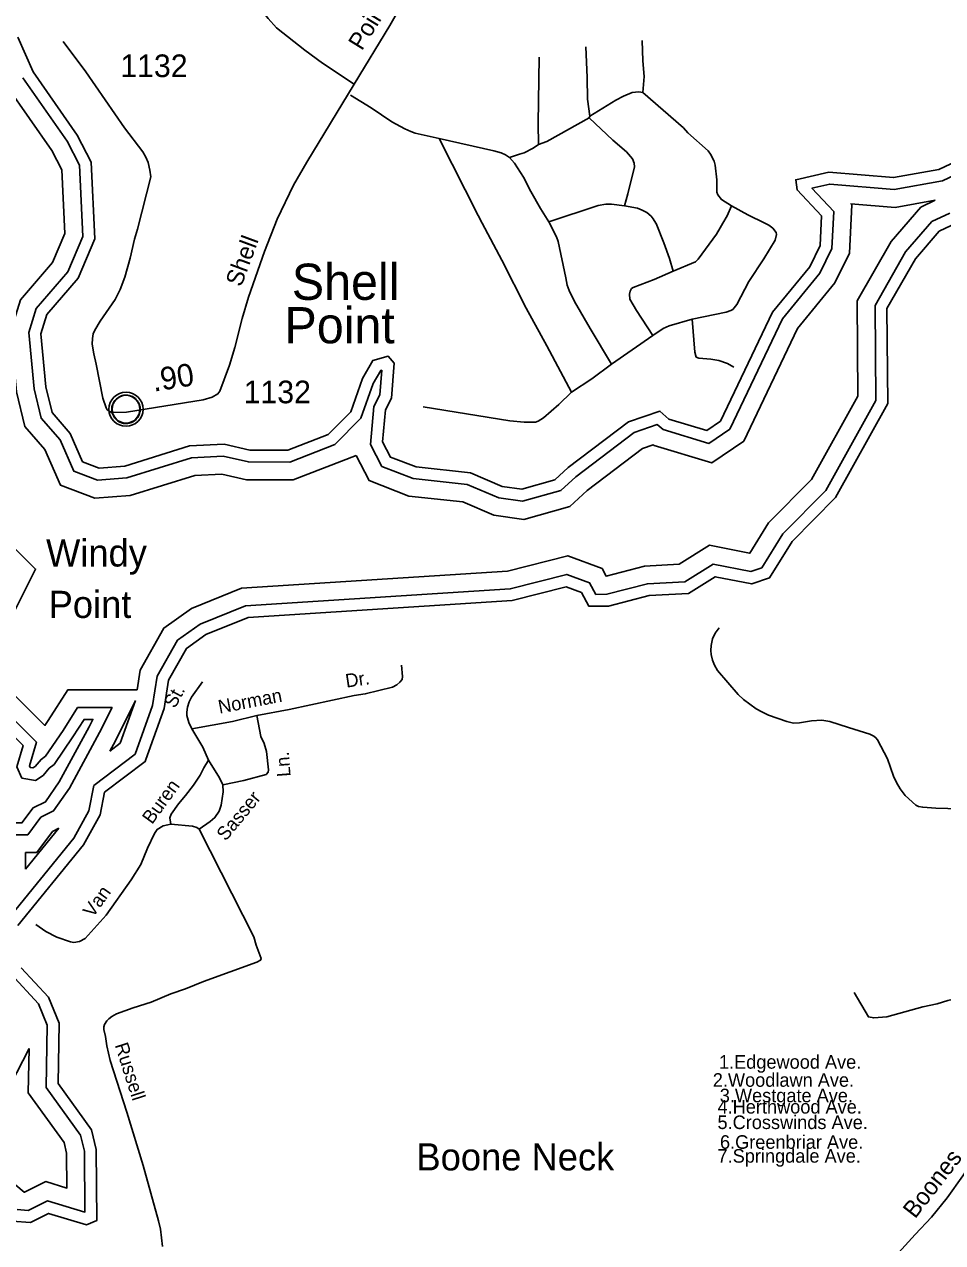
# Model space of a CAD drawing. Extents: x 2104537 to 2336408, y 34176 to 229611.
# Drawn here: x 2193537 to 2198609, y 61547 to 68278 of the extents above; entities that cross this region are included whole.
import ezdxf

# ---------------------------------------------------------------- set-up
doc = ezdxf.new("R2010")
doc.units = 0
for name, color, linetype in [('Exist Civil Demographics Community CELL', 7, 'Continuous'), ('Exist Civil Demographics Community Label', 7, 'Continuous'), ('Exist Hydrographic Buffer Line', 7, 'Continuous'), ('Exist Hydrographic Island Shore', 7, 'Continuous'), ('Exist Hydrographic Point Label', 7, 'Continuous'), ('Exist Hydrographic River Shore', 7, 'Continuous'), ('Exist Road Non-System Type 51', 7, 'Continuous'), ('Exist Road Non-System Type 51 Label', 7, 'Continuous'), ('Exist Road Secondary Mileage Hundredths English Label', 7, 'Continuous'), ('Exist Road Secondary Type 51 Attributed', 7, 'Continuous'), ('Exist Road Secondary Type 51 Label', 7, 'Continuous'), ('Exist Road Secondary Type 51 Number Label', 7, 'Continuous')]:
    doc.layers.add(name, color=color, linetype=linetype)

msp = doc.modelspace()

# ---------------------------------------------------------------- linework, layer by layer
at = {"layer": 'Exist Civil Demographics Community CELL'}
msp.add_lwpolyline([(2194021.1, 66163.6), (2194022.1, 66169.2), (2194023.9, 66175.8), (2194026.8, 66183), (2194029.7, 66188.7), (2194033.1, 66194.5), (2194036.8, 66199.6), (2194040.8, 66204), (2194045.4, 66208.6), (2194050.9, 66213.2), (2194056.3, 66216.8), (2194061.2, 66219.7), (2194066.3, 66222.1), (2194071.7, 66224.4), (2194077.4, 66226.3), (2194081.7, 66227.4), (2194086.5, 66228.1), (2194090.7, 66228.9), (2194097, 66229.1), (2194101.5, 66229), (2194107.1, 66228.8), (2194112, 66228), (2194116.9, 66227), (2194122, 66225.6), (2194127.1, 66223.7), (2194133.8, 66220.8), (2194140, 66217.3), (2194145.1, 66213.7), (2194150.3, 66209.7), (2194153.6, 66206.6), (2194157.7, 66202.2), (2194161.6, 66197.5), (2194164.6, 66192.9), (2194167.8, 66187.9), (2194170.2, 66182.7), (2194172.3, 66177.7), (2194173.8, 66172.7), (2194175.1, 66168.1), (2194176.2, 66162.1), (2194176.8, 66157.4), (2194177.1, 66151.4), (2194176.9, 66145.6), (2194176.3, 66139.9), (2194175.4, 66134.4), (2194173.7, 66128.3), (2194171.9, 66122.4), (2194169.6, 66117.4), (2194166.4, 66111.4), (2194163.1, 66106), (2194159.7, 66101.3), (2194155.4, 66096.6), (2194150.2, 66091.6), (2194145.1, 66087.5), (2194140.1, 66084.1), (2194135.8, 66081.6), (2194129, 66078.3), (2194121.8, 66075.6), (2194115.9, 66074.2), (2194109.3, 66072.9), (2194104.9, 66072.4), (2194100.4, 66072.1), (2194094.8, 66072.1), (2194090.5, 66072.5), (2194084.9, 66073.3), (2194079, 66074.6), (2194074.4, 66075.9), (2194069.2, 66077.8), (2194064.6, 66079.7), (2194060.7, 66082), (2194053.9, 66086.1), (2194048.3, 66090.3), (2194043.4, 66094.8), (2194038.9, 66099.7), (2194035.8, 66103.6), (2194032.8, 66107.8), (2194028.7, 66114.9), (2194027, 66118.5), (2194025.2, 66122.5), (2194022.7, 66130.7), (2194021.1, 66137.7), (2194020.4, 66142.9), (2194020.1, 66149.2), (2194020, 66153.9), (2194020.6, 66160.4)], close=True, dxfattribs=at)
for centre, radius in [((2194098.7, 66151.2), 94.3), ((2194098.5, 66151.5), 76.7)]:
    msp.add_circle(centre, radius, dxfattribs=at)
at = {"layer": 'Exist Hydrographic Buffer Line'}
for points in [[(2195369.5, 65896), (2195022.3, 65760.4), (2194764, 65761.3), (2194627.2, 65792.6), (2194478.6, 65785.3), (2194122.5, 65674.7), (2193926.7, 65660.3), (2193736.3, 65731.9), (2193650.3, 65928.4), (2193540.7, 66056.2), (2193493.6, 66247.8), (2193462.4, 66584.7), (2193515, 66756.4), (2193693.3, 66962.7), (2193760.1, 67122.6), (2193743.6, 67473.9), (2193688.7, 67581.4), (2193442.1, 67934.4), (2193346.9, 68149.6), (2193298.6, 68305.6)], [(2198907, 67554.4), (2198608.9, 67412.9), (2198341.8, 67365.4), (2197985.5, 67395.1), (2197887.1, 67372.3), (2198007.7, 67244), (2197997.7, 67038.9), (2197931.4, 66902.8), (2197724.7, 66651.1), (2197433.4, 66040.9), (2197317.8, 65962.2), (2197065.3, 66038.4), (2197033.1, 66066.5), (2196904.9, 66023.1), (2196583.8, 65778.6), (2196500.5, 65702.7), (2196289.5, 65642.4), (2196157.8, 65660.8), (2195983.9, 65735.9), (2195685.1, 65767.8), (2195511.8, 65835.2), (2195448.8, 65957.1), (2195467.6, 66165.6), (2195500.4, 66230.1), (2195511, 66366.6), (2195506.5, 66365.3), (2195464.5, 66292.5), (2195396.6, 66101.9), (2195252.7, 65956.1), (2195004, 65858.9), (2194775.2, 65859.7), (2194635.9, 65891.5), (2194461.3, 65882.9), (2194104, 65772), (2193941.1, 65760), (2193809.8, 65809.4), (2193734.5, 65981.3), (2193630.7, 66102.5), (2193590.9, 66264.2), (2193562.2, 66574.4), (2193603.1, 66707.7), (2193778.1, 66910.3), (2193859.4, 67105.1), (2193840.9, 67499.8), (2193773.3, 67632.2), (2193528.2, 67982.9)], [(2194159.6, 64601.1), (2194176.1, 64708.9), (2194307.8, 64941.9), (2194460.2, 65051.1), (2194735.9, 65162.3), (2196205.1, 65256.3), (2196538.9, 65341.4), (2196727.9, 65271.2), (2196750.8, 65229.7), (2196963.4, 65284.5), (2197153.9, 65295.3), (2197322.2, 65399.6), (2197543.2, 65355.7), (2197544.8, 65356.2), (2197648.1, 65523.6), (2197885.5, 65762.3), (2198141.4, 66224), (2198137.5, 66750), (2198324.2, 67078.3), (2198489.4, 67268.1), (2198568.2, 67305.7)], [(2198568.2, 67305.7), (2198346.4, 67266.3), (2198102.7, 67286.6), (2198108, 67280.9), (2198095, 67013.9), (2198014.8, 66849.3), (2197808.3, 66597.9), (2197510.7, 65974.5), (2197334.3, 65854.4), (2197016.6, 65950.3), (2197011, 65955.2), (2196951.7, 65935.1), (2196646.8, 65702.9), (2196549.7, 65614.4), (2196296.5, 65542.1), (2196131, 65565.1), (2195958.6, 65639.6), (2195661.7, 65671.3), (2195441.5, 65756.9), (2195369.5, 65896)], [(2194148.6, 64244.7), (2194245.8, 64513.6), (2194270.7, 64676.2), (2194382.7, 64874.6), (2194508, 64964.3), (2194758, 65065.1), (2196220.6, 65158.7), (2196533.4, 65238.5), (2196659.4, 65191.7), (2196694.2, 65128.5), (2196755.1, 65129.1), (2196978.6, 65186.8), (2197184.5, 65198.4), (2197341.1, 65295.5), (2197550.2, 65254), (2197610.1, 65274.7), (2197725.9, 65462.3), (2197964.9, 65702.6), (2198240, 66198.9), (2198236.1, 66724.3), (2198404.9, 67021.1), (2198550.2, 67188), (2198648.8, 67235)], [(2192699.6, 65357.9), (2192995.2, 65136.1), (2193188.5, 65007.1), (2193476, 65021.5), (2193599.1, 65268), (2193420.8, 65446.5), (2193358.9, 65454.2), (2193320.5, 65487.2), (2193152.1, 65534), (2193025.9, 65553.4), (2192788, 65510.1)], [(2194159.6, 64601.1), (2193777.8, 64601.1), (2193668.6, 64431.2), (2193650.4, 64404.4), (2193447.7, 64607.3)], [(2193468.3, 64447.3), (2193329.6, 64209.4), (2193270.3, 64114.3), (2193335.3, 64038.3), (2193349.4, 64000.8), (2193363.2, 63904.4), (2193402.3, 63800.1), (2193556.2, 63800.1), (2193628.5, 63896.6), (2193698.6, 63931.6), (2193785.8, 64058.5), (2193953.1, 64365.4), (2194021.7, 64502.7), (2193831.5, 64502.7), (2193750.7, 64376.9), (2193654.2, 64235.2), (2193629.2, 64216.5), (2193596, 64176.6), (2193584.7, 64169.1), (2193569.3, 64171.9), (2193565.6, 64180.1), (2193604.2, 64311.4), (2193468.3, 64447.3)], [(2194009.1, 64262.6), (2194040.3, 64319.8), (2194151.6, 64542.5)], [(2194065.9, 64305.6), (2194151.6, 64542.5)], [(2194009.1, 64262.6), (2194065.9, 64305.6)], [(2193441.6, 63329.1), (2193810.1, 63781.6), (2193893.3, 63933), (2193920.1, 64071.7), (2194148.6, 64244.7)], [(2193543, 63609.4), (2193727.5, 63836)], [(2193543, 63701.7), (2193605.5, 63701.7), (2193693.4, 63818.9), (2193727.5, 63836)], [(2193543, 63609.4), (2193543, 63701.7)], [(2193496.8, 61729.4), (2193557.7, 61724.2), (2193664.6, 61778.2), (2193871.8, 61715.7), (2193869.1, 62052.4), (2193847.8, 62141.2), (2193657.7, 62404.6), (2193663.8, 62747.4), (2193614.6, 62866.2), (2193461.7, 63031.8)], [(2193127.9, 62215.9), (2193349.7, 62043.5), (2193349.7, 61980.8), (2193536.1, 61824.8), (2193538.2, 61824.7), (2193655.4, 61883.9), (2193772.3, 61848.5), (2193770.8, 62040.4), (2193756.6, 62099.4), (2193558.7, 62373.6), (2193563.1, 62619.7)], [(2193214, 62463.2), (2193390.5, 62286.6), (2193563.1, 62619.7)]]:
    msp.add_lwpolyline(points, dxfattribs=at)
at = {"layer": 'Exist Hydrographic Island Shore'}
msp.add_lwpolyline([(2193482.1, 64340.7), (2193385.8, 64175.5), (2193351.4, 64120.4), (2193392.7, 64072.2), (2193413.3, 64017.1), (2193427.1, 63920.8), (2193447.7, 63865.7), (2193523.4, 63865.7), (2193585.3, 63948.3), (2193654.1, 63982.7), (2193729.8, 64092.9), (2193894.9, 64395.8), (2193915.5, 64437.1), (2193867.4, 64437.1), (2193805.5, 64340.7), (2193702.3, 64189.2), (2193674.8, 64168.6), (2193640.4, 64127.3), (2193599.1, 64099.8), (2193523.4, 64113.5), (2193495.9, 64175.5), (2193530.3, 64292.5), (2193482.1, 64340.7)], dxfattribs=at)
at = {"layer": 'Exist Hydrographic River Shore'}
for points in [[(2198887.7, 67617.8), (2198588.7, 67475.9), (2198338.8, 67431.5), (2197980.8, 67461.4), (2197797.9, 67419), (2197805.8, 67363.1), (2197940.8, 67219.4), (2197932.8, 67055.5), (2197875.8, 66938.5), (2197668.9, 66686.6), (2197381.8, 66085.2), (2197306.8, 66034.1), (2197097.8, 66097.2), (2197047.8, 66140.8), (2196873.7, 66081.8), (2196541.7, 65829), (2196467.7, 65761.6), (2196284.8, 65709.3), (2196175.7, 65724.5), (2196000.8, 65800.1), (2195700.8, 65832.1), (2195558.7, 65887.3), (2195515.8, 65970.2), (2195531.8, 66147.1), (2195564.8, 66212), (2195579.8, 66405.3), (2195545.8, 66445.3), (2195462.7, 66420.7), (2195404.7, 66320.1), (2195339.7, 66137.7), (2195215.8, 66012.1), (2194991.7, 65924.5), (2194782.8, 65925.3), (2194641.7, 65957.5), (2194449.8, 65948.1), (2194091.7, 65836.9), (2193950.7, 65826.5), (2193858.8, 65861.1), (2193790.7, 66016.6), (2193690.7, 66133.3), (2193655.8, 66275.1), (2193628.7, 66567.6), (2193661.7, 66675.3), (2193834.6, 66875.3), (2193925.6, 67093.4), (2193905.8, 67517), (2193829.7, 67666.1), (2193585.7, 68015.3), (2193500.8, 68207.2)], [(2194207.8, 64215.5), (2194309.7, 64497.4), (2194333.7, 64654.4), (2194432.7, 64829.7), (2194539.8, 64906.3), (2194772.7, 65000.3), (2196230.8, 65093.6), (2196529.8, 65169.8), (2196613.7, 65138.7), (2196655.7, 65062.4), (2196763.8, 65063.6), (2196988.7, 65121.6), (2197204.8, 65133.8), (2197353.7, 65226.1), (2197554.9, 65186.2), (2197653.7, 65220.3), (2197777.8, 65421.3), (2198017.9, 65662.8), (2198305.8, 66182.2), (2198301.9, 66707.2), (2198458.7, 66983), (2198590.8, 67134.7), (2198656.8, 67166.2)], [(2193501.8, 63299.1), (2193864.7, 63744.8), (2193955.8, 63910.4), (2193979.8, 64034.6), (2194203.7, 64204.2), (2194207.8, 64215.5)], [(2193470.6, 61665.8), (2193570.7, 61657.3), (2193670.8, 61707.8), (2193879.7, 61644.8), (2193937.7, 61669.9), (2193934.7, 62060.4), (2193908.6, 62169.1), (2193723.7, 62425.3), (2193729.6, 62759.9), (2193670.8, 62902.1), (2193519.6, 63065.8)]]:
    msp.add_lwpolyline(points, dxfattribs=at)
at = {"layer": 'Exist Road Non-System Type 51'}
for p, q in [((2196657, 67762.1), (2196661.1, 67769.9)), ((2196434.6, 67187.4), (2196438.7, 67179.1)), ((2197009.1, 66558.8), (2196781, 66399.8))]:
    msp.add_line(p, q, dxfattribs=at)
for points in [[(2196949.3, 68187.9), (2196952.8, 68076), (2196960, 67990.2), (2196953.3, 67901.8)], [(2196637.7, 68153.9), (2196646.2, 67983.8), (2196647.5, 67864), (2196661.1, 67769.9)], [(2196380.3, 68096.5), (2196375.6, 67730.5), (2196376.9, 67614.7)], [(2195828.4, 67647.2), (2195696.7, 67676.3), (2195671.6, 67685.3), (2195639.4, 67701.1), (2195567, 67739.8), (2195452, 67816.2), (2195338.9, 67887)], [(2196953.3, 67901.8), (2196931.1, 67904.2), (2196895.3, 67901.2), (2196846.6, 67881.2), (2196803.5, 67858.1), (2196661.1, 67769.9)], [(2196953.3, 67901.8), (2197177.9, 67706.8), (2197202.3, 67679.1), (2197313.6, 67578.5), (2197328, 67560.9), (2197347.9, 67522.4), (2197353.7, 67500.3), (2197361.7, 67419.2), (2197362.7, 67351.2), (2197367, 67335.4), (2197387.1, 67309.7), (2197443.5, 67274.5)], [(2196376.9, 67614.7), (2196422.9, 67631.2), (2196657, 67762.1)], [(2196851.4, 67274.5), (2196870.7, 67340.7), (2196906.7, 67491.2), (2196906.4, 67511.3), (2196896.1, 67535.1), (2196863.7, 67572.8), (2196788.5, 67637.9), (2196657, 67762.1)], [(2196217.7, 67542.3), (2196195.7, 67556.5), (2196171.6, 67567.8), (2196131.2, 67579.4), (2195828.4, 67647.2)], [(2195828.4, 67647.2), (2196043.9, 67222.1), (2196066.7, 67179)], [(2196376.9, 67614.7), (2196347.3, 67594.2), (2196297.6, 67567.6), (2196271.6, 67561.2), (2196217.7, 67542.3)], [(2196217.7, 67542.3), (2196244, 67510.6), (2196293.4, 67433.2), (2196334.5, 67354), (2196387.5, 67260.4), (2196434.6, 67187.4)], [(2196851.4, 67274.5), (2196779.4, 67283.7), (2196749.5, 67283.3), (2196706.1, 67277.6), (2196434.6, 67187.4)], [(2197025.2, 67179.3), (2197011.1, 67202.8), (2196999.2, 67217.5), (2196976, 67238.3), (2196949.7, 67251.9), (2196923.9, 67261.6), (2196851.4, 67274.5)], [(2197443.5, 67274.5), (2197418.5, 67219.9), (2197395.7, 67179.4)], [(2197443.5, 67274.5), (2197534.1, 67225.5), (2197627.6, 67179.5)], [(2196066.7, 67179), (2196175.3, 66973.9), (2196308.6, 66709.8), (2196423.4, 66500.9), (2196558.9, 66244.7)], [(2196438.7, 67179.1), (2196475.7, 67103.9), (2196486, 67077.8), (2196528.7, 66876.5), (2196535.2, 66836.3), (2196545.7, 66806.6), (2196576.4, 66747), (2196662.4, 66596.4), (2196781, 66399.8)], [(2197120.3, 66914.3), (2197101.3, 66983.9), (2197070.2, 67071.4), (2197026.6, 67176.9), (2197025.2, 67179.3)], [(2197395.7, 67179.4), (2197381.2, 67153.7), (2197359.5, 67119.3), (2197259.7, 66979.9), (2197243.7, 66965.7), (2197120.3, 66914.3)], [(2197627.6, 67179.5), (2197649.2, 67168.9), (2197671.5, 67151), (2197689.7, 67127.7), (2197691.8, 67117.5), (2197684.3, 67085.2), (2197621.6, 66982.4), (2197539.2, 66857.7), (2197473.1, 66730.7), (2197449.9, 66702.9), (2197439.3, 66696.2), (2197413.2, 66687.9), (2197225.8, 66649.5)], [(2197120.3, 66914.3), (2197016.8, 66868.7), (2196900.4, 66823.7), (2196891.1, 66818), (2196883.6, 66803), (2196880, 66787), (2196882.1, 66759.1), (2196919, 66697.4), (2197009.1, 66558.8)], [(2197225.8, 66649.5), (2197098.7, 66611.9), (2197066.6, 66597.4), (2197009.1, 66558.8)], [(2197455.6, 66384.5), (2197421.2, 66403.9), (2197372.6, 66420.6), (2197328.8, 66428.7), (2197262.6, 66434.2), (2197248.6, 66439.7), (2197240.3, 66465.8), (2197225.8, 66649.5)], [(2196781, 66399.8), (2196672.2, 66318.3), (2196558.9, 66244.7)], [(2196558.9, 66244.7), (2196490, 66178.1), (2196404.6, 66104.3), (2196375, 66084.5), (2196361.1, 66080.2), (2196297.5, 66079.8), (2196218.9, 66086.5), (2195739.7, 66164.3)], [(2198704.1, 63942.8), (2198572, 63947), (2198499.9, 63952.3), (2198475.7, 63956.4), (2198461.7, 63963.6), (2198403, 64016.9), (2198374.6, 64054.5), (2198353.9, 64088.4), (2198337.5, 64124.1), (2198304.3, 64219.2), (2198248.9, 64325), (2198240.6, 64336), (2198229.3, 64345.7), (2198206.5, 64356.3), (2198089.8, 64392.7), (2197985.4, 64425.5), (2197941.6, 64432.9), (2197885.4, 64430.1), (2197817.9, 64417.9), (2197785.4, 64417.6), (2197749.2, 64425.8), (2197646.8, 64460.9), (2197610.8, 64478.7), (2197578.6, 64496), (2197509.7, 64547.2), (2197479.4, 64575), (2197365.5, 64707.5), (2197349.4, 64737.6), (2197338.7, 64765.1), (2197331.1, 64797), (2197329.3, 64819.1), (2197330.5, 64846.6), (2197337.4, 64882.9), (2197352.7, 64913.4), (2197374.7, 64943.5)], [(2195620.7, 64736.8), (2195626, 64675.4), (2195623.8, 64658.7), (2195612, 64642.5), (2195595, 64628.7), (2195570.1, 64616.1), (2195420.1, 64578.3), (2195358.9, 64569.3), (2194999.8, 64492.6), (2194822, 64458.6)], [(2194463, 64385.8), (2194445.9, 64420.9), (2194433.9, 64459.5), (2194433.9, 64477.6), (2194438.4, 64506), (2194447.5, 64535.4), (2194460.8, 64559.7), (2194521.4, 64644.5)], [(2194822, 64458.6), (2194686.5, 64426.8), (2194463, 64385.8)], [(2194822, 64458.6), (2194843.7, 64342.7), (2194862.3, 64304.9), (2194874.9, 64260.7), (2194886.1, 64159.1), (2194884.2, 64145.4), (2194872.5, 64133.1), (2194748.8, 64099.4), (2194633.2, 64076.1)], [(2194463, 64385.8), (2194522.4, 64284.6), (2194555.1, 64213.1)], [(2194555.1, 64213.1), (2194527.7, 64170.6), (2194508.2, 64130.3), (2194471.1, 64074), (2194428, 64017.4), (2194388.4, 63970.9), (2194347.3, 63914.3), (2194341.3, 63894), (2194345.8, 63858.2)], [(2194555.1, 64213.1), (2194614.6, 64113.8), (2194633.2, 64076.1)], [(2194633.2, 64076.1), (2194635.7, 64038), (2194624.1, 63964.4), (2194614, 63930.8), (2194589.4, 63895.5), (2194564, 63873), (2194502.1, 63830.2)], [(2193600.9, 63304.6), (2193655.6, 63265.5), (2193716, 63234.2), (2193792, 63208.4), (2193810.3, 63205.5), (2193841.2, 63210.1), (2193873.1, 63227.5), (2193988.4, 63355.6), (2194128, 63551.4), (2194180.8, 63636), (2194217.7, 63726.5), (2194256.6, 63807.1), (2194270.2, 63829.5), (2194304, 63849.8), (2194345.8, 63858.2)], [(2194300.6, 61525.7), (2194289.3, 61621.4), (2194278.7, 61667.5), (2194192.7, 61972.4), (2194102.9, 62267.1), (2194011, 62553.9), (2193991.9, 62633.7), (2193985, 62685), (2193976.5, 62723.6), (2193976.8, 62739.3), (2193980.3, 62751.4), (2193992.2, 62771.8), (2194003.9, 62783.7), (2194019.9, 62796.2), (2194045.5, 62810.5), (2194137.3, 62843.8), (2194236.7, 62875.1), (2194346.2, 62922.2), (2194427.7, 62949.5), (2194527.2, 62988.6), (2194822, 63096.4), (2194842.2, 63106.5), (2194846, 63116.9), (2194816.9, 63190.3), (2194804.3, 63236.2), (2194502.1, 63830.2)], [(2194502.1, 63830.2), (2194490.2, 63840), (2194466.1, 63847.7), (2194345.8, 63858.2)], [(2199518.4, 63025.2), (2199468.3, 63026.9), (2199356.3, 63037.2), (2199174.4, 63015.1), (2199092.8, 62999.6), (2198759.7, 62911.6), (2198638.1, 62884.1), (2198578.4, 62865.2), (2198500.3, 62850.3), (2198301.1, 62793.8), (2198229.1, 62788.6), (2198199, 62794.1), (2198121.3, 62929.5)]]:
    msp.add_lwpolyline(points, dxfattribs=at)
at = {"layer": 'Exist Road Secondary Type 51 Attributed'}
for points in [[(2196897.3, 70613.2), (2196765.7, 70473.5), (2196680.7, 70368.3), (2196465.7, 70125.4), (2196311.6, 69995.5), (2196174, 69891.1), (2195907.2, 69671), (2195834.5, 69598.3), (2195803.3, 69556.7), (2195777.3, 69513.3), (2195742.6, 69442.2), (2195729.7, 69405.3), (2195717.8, 69347.8), (2195706.3, 69273.8), (2195701.1, 69178.5), (2195704.6, 69050.6), (2195716.3, 68819.1), (2195718.5, 68692.5), (2195705.5, 68611.5), (2195692, 68557.3), (2195667.3, 68481.4), (2195641.9, 68424.8), (2195555.6, 68272.2), (2195358.5, 67947.7)], [(2195358.5, 67947.7), (2195184.8, 68062.8), (2195085.5, 68135.6), (2194930, 68257.7), (2194883.1, 68309.1), (2194758.4, 68468.4), (2193864.6, 69476.7)], [(2195358.5, 67947.7), (2195096.6, 67516.7), (2195023.8, 67388.4), (2194933.8, 67201.3), (2194862.7, 67022.8), (2194774.8, 66769.5), (2194740.4, 66652.4), (2194699.1, 66492.8), (2194669.5, 66394.2), (2194617.5, 66251.5), (2194606.7, 66235.4), (2194575.2, 66217), (2194525, 66203.1), (2194100.9, 66135.7), (2194018.3, 66132.6), (2193994.8, 66148), (2193988.2, 66158.7), (2193970.9, 66212), (2193934.3, 66400.6), (2193920.4, 66457.8), (2193911.8, 66511.6), (2193913.5, 66542.7), (2193917, 66568.7), (2193925.6, 66587.8), (2193955.1, 66638.1), (2194039.1, 66758.2), (2194065.9, 66812.3), (2194091.9, 66880.7), (2194121.4, 66986.4), (2194145.4, 67090.5), (2194162.9, 67145.3), (2194235.1, 67435.5), (2194231, 67471.6), (2194220.7, 67513.6), (2194207.3, 67544.7), (2194190.7, 67573.8), (2194090.1, 67706), (2193877.1, 68015.4), (2193751.6, 68183)], [(2199512.3, 62915.6), (2199340.2, 62713.8), (2199136, 62481.1), (2198995.9, 62306.4), (2198880.3, 62151.4), (2198720.4, 61915.2), (2198634.4, 61794.6), (2198548.3, 61686.9), (2198457.3, 61590.9), (2198366.3, 61490.1), (2198238.4, 61381.8), (2198137.1, 61267.7), (2198076.1, 61198.7), (2198059.9, 61176), (2198036.2, 61134.8), (2197994.2, 61049.7), (2197972.8, 60997.3), (2197953.6, 60939.2), (2197886.7, 60641.2), (2197842.5, 60459.2), (2197822.8, 60353.4), (2197810, 60280.2)]]:
    msp.add_lwpolyline(points, dxfattribs=at)

# ---------------------------------------------------------------- texts
at = {"layer": 'Exist Civil Demographics Community Label'}
for s, p in [('Shell', (2195014.5, 66755.5)), ('Point', (2194974, 66515.5))]:
    msp.add_text(s, height=200, dxfattribs=at).set_placement(p)
at = {"layer": 'Exist Hydrographic Point Label'}
for s, p in [('Windy ', (2193656.9, 65282.3)), ('Point', (2193671.3, 64998)), ('Boone Neck', (2195702.8, 61945.7))]:
    msp.add_text(s, height=150, dxfattribs=at).set_placement(p)
at = {"layer": 'Exist Road Non-System Type 51 Label'}
for s, rotation, p in [('Dr.', 8.35961, (2195316.2, 64612.8)), ('St.', 61.42146, (2194369.2, 64494.5)), ('Norman', 10.81611, (2194615.2, 64469.2)), ('Ln.', 94.35131, (2195008.2, 64122.8)), ('Buren', 54.01232, (2194242.6, 63853.9)), ('Sasser', 50.39838, (2194649.4, 63761.4)), ('Van', 54.51212, (2193915.7, 63338.4)), ('Russell', 287.76481, (2194035.7, 62638.3))]:
    msp.add_text(s, height=75, rotation=rotation, dxfattribs=at).set_placement(p)
for s, p in [('1.Edgewood Ave.', (2197373.9, 62507.7)), ('2.Woodlawn Ave.', (2197339.8, 62407.9)), ('3.Westgate Ave.', (2197378.4, 62322.2)), ('4.Herthwood Ave.', (2197366, 62259.9)), ('5.Crosswinds Ave.', (2197365.8, 62174.2)), ('6.Greenbriar Ave.', (2197379.5, 62065.1)), ('7.Springdale Ave.', (2197366, 61988.5))]:
    msp.add_text(s, height=75, dxfattribs=at).set_placement(p)
at = {"layer": 'Exist Road Secondary Mileage Hundredths English Label'}
msp.add_text('.90', height=125, rotation=9.02728, dxfattribs=at).set_placement((2194252.1, 66247.9))
at = {"layer": 'Exist Road Secondary Type 51 Label'}
for s, rotation, p in [('Point', 58.30408, (2195401.5, 68128.1)), ('Shell', 69.71034, (2194735, 66822.9)), ('Boones', 52.16976, (2198457.3, 61674.6))]:
    msp.add_text(s, height=95, rotation=rotation, dxfattribs=at).set_placement(p)
at = {"layer": 'Exist Road Secondary Type 51 Number Label'}
for p in [(2194066.9, 67986.3), (2194748.2, 66184.2)]:
    msp.add_text('1132', height=125, dxfattribs=at).set_placement(p)

doc.saveas('drawing.dxf')
